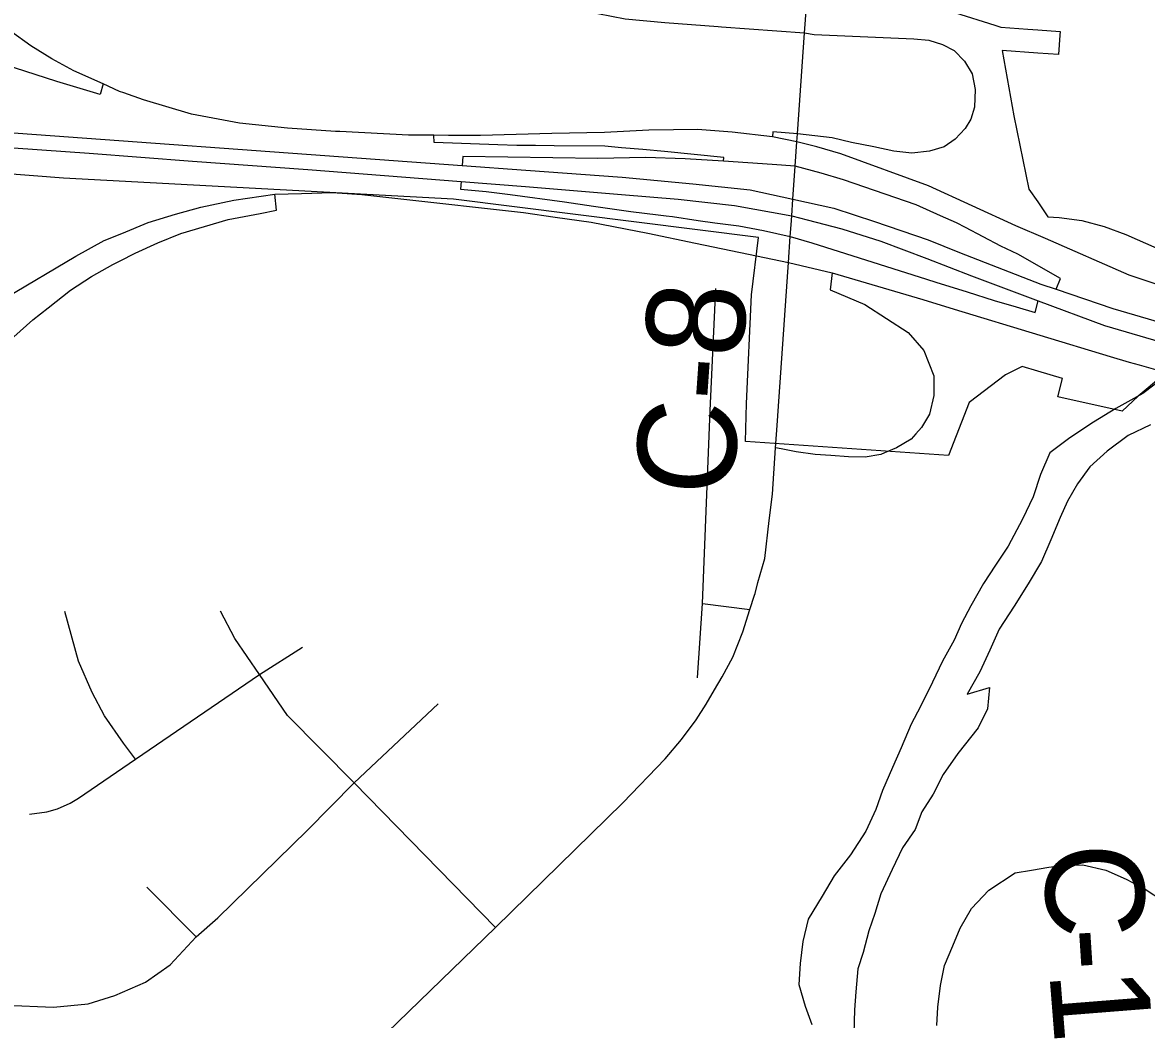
# Model space of a CAD drawing. Extents: x 208586767.6 to 208586821.4, y -134301046.9 to -134301022.9.
# Drawn here: x 208586778.552 to 208586779.201, y -134301025.698 to -134301025.123 of the extents above; entities that cross this region are included whole.
import ezdxf

# ---------------------------------------------------------------- set-up
doc = ezdxf.new("R2010")
doc.units = 0
for name, color, linetype in [('GM_X_City_Street', 7, 'Continuous'), ('GM_X_Corporation', 7, 'Continuous'), ('GM_X_County_Road', 7, 'Continuous'), ('GM_X_County_Road_Text', 7, 'Continuous'), ('GM_X_Interchange_Ramps', 7, 'Continuous'), ('GM_X_Major_River', 7, 'Continuous'), ('GM_X_Minor_River', 7, 'Continuous'), ('GM_X_State_Route', 7, 'Continuous'), ('GM_X_Township_Road', 7, 'Continuous')]:
    doc.layers.add(name, color=color, linetype=linetype)

msp = doc.modelspace()

# ---------------------------------------------------------------- linework, layer by layer
at = {"layer": 'GM_X_City_Street'}
for p, q in [((208586778.94471, -134301025.45835), (208586778.97201, -134301025.4618)), ((208586778.68918, -134301025.49933), (208586778.71399, -134301025.48353)), ((208586778.74369, -134301025.56174), (208586778.79219, -134301025.51625)), ((208586778.65264, -134301025.65056), (208586778.62409, -134301025.62201))]:
    msp.add_line(p, q, dxfattribs=at)
for points in [[(208586778.94192, -134301025.50126), (208586778.94471, -134301025.45835), (208586778.94916, -134301025.34705), (208586778.95244, -134301025.27678)], [(208586778.61769, -134301025.54811), (208586778.61065, -134301025.53897), (208586778.59979, -134301025.52316), (208586778.59271, -134301025.50971), (208586778.58469, -134301025.49154), (208586778.57691, -134301025.463)], [(208586778.82536, -134301025.64512), (208586778.74369, -134301025.56174), (208586778.70534, -134301025.52302), (208586778.68918, -134301025.49933), (208586778.67489, -134301025.47865), (208586778.66662, -134301025.46286)], [(208586778.5565, -134301025.5799), (208586778.56641, -134301025.57849), (208586778.57266, -134301025.57671), (208586778.57986, -134301025.57342), (208586778.58469, -134301025.5707), (208586778.61769, -134301025.54811), (208586778.68918, -134301025.49933)], [(208586778.45867, -134301025.68422), (208586778.51985, -134301025.68805), (208586778.54289, -134301025.69003), (208586778.57037, -134301025.69107), (208586778.5903, -134301025.68919), (208586778.60571, -134301025.68431), (208586778.62338, -134301025.67679), (208586778.63767, -134301025.66663), (208586778.65264, -134301025.65056), (208586778.66511, -134301025.63957), (208586778.71662, -134301025.58919), (208586778.74369, -134301025.56174)]]:
    msp.add_lwpolyline(points, dxfattribs=at)
at = {"layer": 'GM_X_Corporation'}
for points in [[(208586779.09006, -134301025.11763), (208586779.11339, -134301025.12492), (208586779.11682, -134301025.126), (208586779.13236, -134301025.12716), (208586779.13816, -134301025.1276), (208586779.15101, -134301025.12856), (208586779.15087, -134301025.13065), (208586779.15014, -134301025.14183), (208586779.13816, -134301025.14101), (208586779.11766, -134301025.1396), (208586779.12435, -134301025.1771), (208586779.13308, -134301025.21943), (208586779.13816, -134301025.22686), (208586779.144, -134301025.23539), (208586779.1505, -134301025.23572), (208586779.16364, -134301025.23759), (208586779.17649, -134301025.24092), (208586779.18889, -134301025.24566), (208586779.23117, -134301025.26423)], [(208586779.25447, -134301025.29002), (208586779.19611, -134301025.33876), (208586779.18676, -134301025.34756), (208586779.14968, -134301025.33912), (208586779.15233, -134301025.32865), (208586779.13816, -134301025.32445), (208586779.12915, -134301025.32178), (208586779.11952, -134301025.32651), (208586779.09857, -134301025.3424), (208586779.08663, -134301025.37312), (208586778.96949, -134301025.36497), (208586778.97012, -134301025.34308), (208586778.97309, -134301025.28036), (208586778.97702, -134301025.24735), (208586778.80117, -134301025.22522), (208586778.57617, -134301025.21309), (208586778.38793, -134301025.19854), (208586778.30326, -134301025.19265), (208586778.20883, -134301025.18481), (208586778.0997, -134301025.17959), (208586778.05675, -134301025.1801), (208586778.02826, -134301025.18459), (208586778.02826, -134301030.32371)]]:
    msp.add_lwpolyline(points, dxfattribs=at)
at = {"layer": 'GM_X_County_Road'}
msp.add_line((208586778.98681, -134301025.36855), (208586778.98752, -134301025.35845), dxfattribs=at)
for points in [[(208586778.98752, -134301025.35845), (208586778.9943, -134301025.26173), (208586778.9953, -134301025.24677), (208586778.99583, -134301025.23999), (208586778.99618, -134301025.23494), (208586778.99687, -134301025.22516), (208586778.9982, -134301025.20621), (208586778.99918, -134301025.19215), (208586778.99951, -134301025.18748), (208586779.00359, -134301025.12937), (208586779.00396, -134301025.12431), (208586779.01097, -134301025.02827), (208586779.01558, -134301024.97747), (208586779.01678, -134301024.9652)], [(208586778.97503, -134301025.45268), (208586778.97661, -134301025.44635), (208586778.98062, -134301025.4324), (208586778.98323, -134301025.41059), (208586778.98508, -134301025.39539), (208586778.98681, -134301025.36855)], [(208586778.48186, -134301025.97017), (208586778.6751, -134301025.79061), (208586778.82536, -134301025.64512), (208586778.89868, -134301025.57327), (208586778.92318, -134301025.54795), (208586778.93255, -134301025.53677), (208586778.9411, -134301025.52543), (208586778.94685, -134301025.51639), (208586778.95162, -134301025.50817), (208586778.95606, -134301025.5006), (208586778.96214, -134301025.48926), (208586778.96807, -134301025.47479), (208586778.97201, -134301025.4618), (208586778.9748, -134301025.45358), (208586778.97503, -134301025.45268)]]:
    msp.add_lwpolyline(points, dxfattribs=at)
at = {"layer": 'GM_X_Interchange_Ramps'}
for points in [[(208586778.599, -134301025.15881), (208586778.58213, -134301025.15123), (208586778.56944, -134301025.14427), (208586778.5572, -134301025.13685), (208586778.5336, -134301025.11996), (208586778.51178, -134301025.10066), (208586778.49129, -134301025.07803), (208586778.48975, -134301025.07589), (208586778.47321, -134301025.05299), (208586778.45788, -134301025.02567), (208586778.44564, -134301024.99698), (208586778.43694, -134301024.96739), (208586778.43196, -134301024.93736), (208586778.42939, -134301024.89901), (208586778.42899, -134301024.85724), (208586778.42236, -134301024.85715)], [(208586779.00359, -134301025.12937), (208586779.00921, -134301025.13024), (208586779.06667, -134301025.13278), (208586779.07524, -134301025.13359), (208586779.08319, -134301025.13604), (208586779.08992, -134301025.13951), (208586779.09584, -134301025.14563), (208586779.10032, -134301025.15297), (208586779.10196, -134301025.16194), (208586779.10155, -134301025.17214), (208586779.09951, -134301025.17908), (208586779.09624, -134301025.18458), (208586779.09053, -134301025.1907), (208586779.08421, -134301025.19498), (208586779.07564, -134301025.19764), (208586779.06545, -134301025.19866), (208586779.05504, -134301025.19764), (208586779.04362, -134301025.19498), (208586779.03077, -134301025.19254), (208586779.01955, -134301025.18989), (208586778.99951, -134301025.18748), (208586778.98536, -134301025.18649), (208586778.98511, -134301025.1893)], [(208586778.599, -134301025.15881), (208586778.59716, -134301025.1649), (208586778.57221, -134301025.1574), (208586778.54786, -134301025.14958), (208586778.52502, -134301025.14269), (208586778.51346, -134301025.13988), (208586778.49943, -134301025.13745), (208586778.48507, -134301025.13648), (208586778.4676, -134301025.13823), (208586778.45375, -134301025.14084), (208586778.4379, -134301025.14511), (208586778.42429, -134301025.15052), (208586778.41498, -134301025.15406), (208586778.40597, -134301025.15835), (208586778.39666, -134301025.16313), (208586778.39122, -134301025.16659), (208586778.38741, -134301025.16888), (208586778.38485, -134301025.1713), (208586778.38124, -134301025.17496), (208586778.37293, -134301025.18341), (208586778.36505, -134301025.19353), (208586778.36034, -134301025.20062)], [(208586778.78978, -134301025.18841), (208586778.77514, -134301025.18831), (208586778.73558, -134301025.1863), (208586778.73301, -134301025.18617), (208586778.70529, -134301025.18431), (208586778.67765, -134301025.18143), (208586778.65003, -134301025.17625), (208586778.62233, -134301025.16797), (208586778.61082, -134301025.1639), (208586778.60849, -134301025.16308), (208586778.599, -134301025.15881)], [(208586779.23472, -134301025.28372), (208586779.19093, -134301025.26912), (208586779.14257, -134301025.24801), (208586779.1255, -134301025.24056), (208586779.07515, -134301025.21752), (208586779.02445, -134301025.19906), (208586779.01078, -134301025.19516), (208586778.99918, -134301025.19215), (208586778.98511, -134301025.1893), (208586778.96188, -134301025.18668), (208586778.94191, -134301025.18511), (208586778.92797, -134301025.1853), (208586778.91375, -134301025.18536), (208586778.88814, -134301025.18676), (208586778.85782, -134301025.18741), (208586778.81666, -134301025.18861), (208586778.79812, -134301025.18847), (208586778.78978, -134301025.18841)], [(208586778.95684, -134301025.20337), (208586778.95699, -134301025.20121), (208586778.92289, -134301025.19785), (208586778.91025, -134301025.19661), (208586778.89794, -134301025.19557), (208586778.88842, -134301025.19477), (208586778.85911, -134301025.19455), (208586778.84834, -134301025.19438), (208586778.83757, -134301025.19422), (208586778.82661, -134301025.19382), (208586778.78994, -134301025.19247), (208586778.78978, -134301025.18841)], [(208586778.95684, -134301025.20337), (208586778.93473, -134301025.20191), (208586778.9119, -134301025.2013), (208586778.88426, -134301025.20179), (208586778.8064, -134301025.20073), (208586778.80606, -134301025.20577)], [(208586778.9982, -134301025.20621), (208586778.98499, -134301025.20523), (208586778.95684, -134301025.20337)], [(208586779.09637, -134301025.24158), (208586779.09127, -134301025.23888), (208586779.08209, -134301025.23481), (208586779.06804, -134301025.22858), (208586779.02607, -134301025.21406), (208586779.01311, -134301025.21017), (208586778.9982, -134301025.20621)], [(208586778.80541, -134301025.21512), (208586778.8051, -134301025.21943), (208586778.81996, -134301025.22082), (208586778.83382, -134301025.22252), (208586778.86519, -134301025.22677), (208586778.88184, -134301025.22926), (208586778.90342, -134301025.23231), (208586778.91909, -134301025.23427)], [(208586778.53817, -134301025.31274), (208586778.55834, -134301025.29474), (208586778.56721, -134301025.28784), (208586778.58023, -134301025.27771), (208586778.59219, -134301025.26983), (208586778.6046, -134301025.26287), (208586778.6087, -134301025.26079), (208586778.61743, -134301025.25637), (208586778.63053, -134301025.25045), (208586778.6438, -134301025.2451), (208586778.67114, -134301025.23694), (208586778.68947, -134301025.23347), (208586778.69898, -134301025.23167), (208586778.69796, -134301025.22238)], [(208586778.54297, -134301025.28194), (208586778.58317, -134301025.25814), (208586778.59957, -134301025.24914), (208586778.60982, -134301025.24504), (208586778.62485, -134301025.23878), (208586778.64079, -134301025.23388), (208586778.65537, -134301025.22989), (208586778.67427, -134301025.22591), (208586778.69796, -134301025.22238)], [(208586778.69796, -134301025.22238), (208586778.71341, -134301025.22189), (208586778.73103, -134301025.22136), (208586778.74813, -134301025.22255), (208586778.76891, -134301025.22492), (208586778.84151, -134301025.23294), (208586778.85966, -134301025.2357), (208586778.88044, -134301025.23846), (208586778.91319, -134301025.24478), (208586778.94068, -134301025.25069), (208586778.97134, -134301025.25701)], [(208586778.91909, -134301025.23427), (208586778.92386, -134301025.23487), (208586778.92748, -134301025.23532), (208586778.94222, -134301025.23745), (208586778.95177, -134301025.23885), (208586778.9657, -134301025.24067), (208586778.97992, -134301025.24332), (208586778.9953, -134301025.24677)], [(208586779.14882, -134301025.27721), (208586779.15125, -134301025.27091), (208586779.12658, -134301025.25702), (208586779.11676, -134301025.2524), (208586779.09637, -134301025.24158)], [(208586778.9953, -134301025.24677), (208586779.00787, -134301025.25047), (208586779.07404, -134301025.27139), (208586779.07933, -134301025.27306)], [(208586778.97134, -134301025.25701), (208586778.99434, -134301025.26174), (208586779.01955, -134301025.26766)], [(208586779.01955, -134301025.26766), (208586779.01834, -134301025.2776), (208586779.03842, -134301025.28593), (208586779.06335, -134301025.30204), (208586779.0724, -134301025.31241), (208586779.07814, -134301025.32719), (208586779.07814, -134301025.33844), (208586779.07571, -134301025.34925), (208586779.07114, -134301025.35685), (208586779.06779, -134301025.3606)], [(208586779.01955, -134301025.26766), (208586779.07187, -134301025.28311), (208586779.08982, -134301025.2886), (208586779.13927, -134301025.30375), (208586779.17985, -134301025.316), (208586779.1909, -134301025.31913), (208586779.19658, -134301025.32074), (208586779.20746, -134301025.32382), (208586779.21033, -134301025.32457)], [(208586779.07933, -134301025.27306), (208586779.09733, -134301025.27873), (208586779.11303, -134301025.28363), (208586779.1256, -134301025.28729), (208586779.13667, -134301025.29051), (208586779.13845, -134301025.28379)], [(208586779.06779, -134301025.3606), (208586779.06512, -134301025.36359), (208586779.05674, -134301025.36866), (208586779.0497, -134301025.37158)], [(208586779.0497, -134301025.37158), (208586779.04769, -134301025.37241), (208586779.03865, -134301025.37396), (208586779.02894, -134301025.37374), (208586779.01879, -134301025.37307), (208586779.00974, -134301025.37241), (208586778.99871, -134301025.37087), (208586778.99011, -134301025.3691), (208586778.98681, -134301025.36855)]]:
    msp.add_lwpolyline(points, dxfattribs=at)
at = {"layer": 'GM_X_Major_River'}
for points in [[(208586779.21212, -134301025.32702), (208586779.19879, -134301025.33721), (208586779.18319, -134301025.34587), (208586779.17026, -134301025.35378), (208586779.15656, -134301025.36283), (208586779.14514, -134301025.37151), (208586779.13977, -134301025.38402), (208586779.13553, -134301025.39691), (208586779.1294, -134301025.40979), (208586779.12098, -134301025.42532), (208586779.11371, -134301025.43629), (208586779.10683, -134301025.44689), (208586779.09956, -134301025.45977), (208586779.0942, -134301025.47), (208586779.08998, -134301025.47947), (208586779.0831, -134301025.49159), (208586779.07735, -134301025.50371), (208586779.07045, -134301025.51773), (208586779.06509, -134301025.52796), (208586779.05933, -134301025.5416), (208586779.05434, -134301025.55296), (208586779.04859, -134301025.56623), (208586779.04474, -134301025.57722), (208586779.03899, -134301025.58972), (208586779.0302, -134301025.60335), (208586779.02065, -134301025.61546), (208586779.01377, -134301025.6272)], [(208586779.20325, -134301025.35545), (208586779.19032, -134301025.36147), (208586779.17814, -134301025.37053), (208586779.16823, -134301025.37959), (208586779.16098, -134301025.38943), (208586779.15524, -134301025.39928)], [(208586779.15524, -134301025.39928), (208586779.15102, -134301025.40875), (208586779.14565, -134301025.42163), (208586779.14028, -134301025.43414), (208586779.13263, -134301025.44701), (208586779.1246, -134301025.45988), (208586779.11581, -134301025.47313), (208586779.11044, -134301025.48526), (208586779.10468, -134301025.49776), (208586779.09741, -134301025.51064), (208586779.11033, -134301025.5069), (208586779.10913, -134301025.51904), (208586779.10377, -134301025.53003), (208586779.09194, -134301025.54478), (208586779.08353, -134301025.55689), (208586779.07779, -134301025.56826), (208586779.07129, -134301025.57848), (208586779.06744, -134301025.58871), (208586779.06018, -134301025.59931), (208586779.05405, -134301025.61182), (208586779.04753, -134301025.62583), (208586779.04406, -134301025.63721), (208586779.0406, -134301025.64707), (208586779.0375, -134301025.65958), (208586779.03442, -134301025.66906), (208586779.03322, -134301025.68234), (208586779.03241, -134301025.69259), (208586779.03196, -134301025.70626)], [(208586779.01377, -134301025.6272), (208586779.00574, -134301025.64045), (208586779.00264, -134301025.65335), (208586779.00106, -134301025.66587), (208586779.00024, -134301025.67802), (208586779.00397, -134301025.69056), (208586779.00771, -134301025.70121)]]:
    msp.add_lwpolyline(points, dxfattribs=at)
at = {"layer": 'GM_X_Minor_River'}
msp.add_lwpolyline([(208586779.07992, -134301025.70168), (208586779.0804, -134301025.69105), (208586779.08203, -134301025.67854), (208586779.08441, -134301025.66717), (208586779.08906, -134301025.65582), (208586779.09332, -134301025.6456), (208586779.09987, -134301025.63427), (208586779.10982, -134301025.62373), (208586779.12507, -134301025.61362), (208586779.13456, -134301025.61219), (208586779.14443, -134301025.61038), (208586779.15391, -134301025.60933), (208586779.16415, -134301025.60905), (208586779.17739, -134301025.61221), (208586779.18909, -134301025.61725), (208586779.20003, -134301025.62305), (208586779.21058, -134301025.62999)], dxfattribs=at)
at = {"layer": 'GM_X_State_Route'}
for points in [[(208586778.35359, -134301025.18168), (208586778.37293, -134301025.18341), (208586778.38637, -134301025.18461), (208586778.40453, -134301025.18582), (208586778.413, -134301025.18637), (208586778.45549, -134301025.18914), (208586778.48147, -134301025.19092), (208586778.50445, -134301025.1924), (208586778.53345, -134301025.19467), (208586778.59086, -134301025.19881), (208586778.65054, -134301025.20335), (208586778.71702, -134301025.20808), (208586778.80541, -134301025.21512), (208586778.84259, -134301025.21795), (208586778.89808, -134301025.22255), (208586778.93076, -134301025.22518), (208586778.96322, -134301025.22891), (208586778.99618, -134301025.23494), (208586779.00515, -134301025.23722)], [(208586778.49958, -134301025.18348), (208586778.80606, -134301025.20577), (208586778.84285, -134301025.20849), (208586778.89838, -134301025.21248), (208586778.93909, -134301025.21641), (208586778.97221, -134301025.21992), (208586778.99687, -134301025.22516), (208586779.02058, -134301025.23038), (208586779.04393, -134301025.23812), (208586779.07491, -134301025.24877), (208586779.09295, -134301025.25608), (208586779.13999, -134301025.27423), (208586779.14882, -134301025.27721)], [(208586779.00515, -134301025.23722), (208586779.02507, -134301025.24229), (208586779.04766, -134301025.24953), (208586779.0742, -134301025.2594), (208586779.09986, -134301025.26949), (208586779.13845, -134301025.28379), (208586779.17663, -134301025.298), (208586779.22071, -134301025.31094), (208586779.27066, -134301025.32147)], [(208586779.14882, -134301025.27721), (208586779.18136, -134301025.28821), (208586779.22555, -134301025.30117), (208586779.26886, -134301025.30982)]]:
    msp.add_lwpolyline(points, dxfattribs=at)
at = {"layer": 'GM_X_Township_Road'}
msp.add_line((208586778.95577, -134301025.12579), (208586779.00359, -134301025.12937), dxfattribs=at)
msp.add_lwpolyline([(208586778.56683, -134301025.0137), (208586778.56889, -134301025.02316), (208586778.57205, -134301025.0318), (208586778.57987, -134301025.04457), (208586778.58397, -134301025.04918), (208586778.59386, -134301025.05788), (208586778.6047, -134301025.06309), (208586778.61595, -134301025.0657), (208586778.66233, -134301025.07036), (208586778.69815, -134301025.07426), (208586778.71931, -134301025.07869), (208586778.75958, -134301025.08768), (208586778.88434, -134301025.11823), (208586778.90017, -134301025.1212), (208586778.92293, -134301025.12343), (208586778.95385, -134301025.12565), (208586778.95577, -134301025.12579)], dxfattribs=at)

# ---------------------------------------------------------------- texts
at = {"layer": 'GM_X_County_Road_Text'}
for s, height, rotation, p in [('C-8', 0.056818, 86.01504, (208586778.96217, -134301025.39752)), ('C', 0.05682, 270.88994, (208586779.14232, -134301025.59682)), ('-', 0.05682, 273.69405, (208586779.14316, -134301025.64651)), ('1', 0.05682, 274.53803, (208586779.14473, -134301025.67071))]:
    msp.add_text(s, height=height, rotation=rotation, dxfattribs=at).set_placement(p)

doc.saveas('drawing.dxf')
